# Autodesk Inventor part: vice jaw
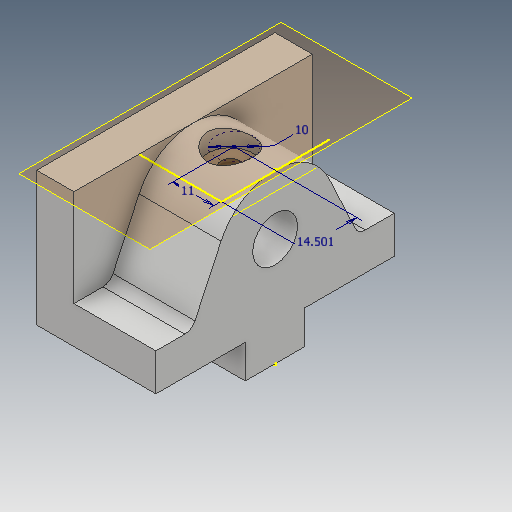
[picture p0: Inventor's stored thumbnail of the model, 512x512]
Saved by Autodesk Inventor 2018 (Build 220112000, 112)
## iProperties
Created: 2016-03
Part Number: vice jaw
Material: Generic
Document SubType Name: Modeling
Designer: Sandeep
Density: 1 g/cm^3
Appearance: Default
Author: Sandeep
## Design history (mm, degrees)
sketch "Sketch1"
  geometry: L1 (0, 0)-(-32, 0); L2 (-32, 0)-(-32, 36); L3 (-32, 36)-(-22, 36); L4 (-22, 36)-(-22, 10); L5 (-22, 10)-(0, 10); L6 (0, 10)-(0, 0)
  constraints: 12 end point, 5 perpendicular, 1 horizontal
  dimensions: "d0" = 36 distance between parallel lines of L1 L3; "d1" = 32 distance of L1.start L1.end; "d2" = 10 distance of L5.end L1.start; "d3" = 10 distance of L2.end L3.end
extrude "Extrusion1" new body sketch "Sketch1" stored distance "d4" = 64; taper "d5" = 0 deg
sketch "Sketch2"
  geometry: L1 (64, 10)-(64, 0) reference; L2 (64, 10)-(64, 0); L3 (64, 0)-(54.317, 0); L4 (64, 0)-(0, 0) reference; L5 (54.317, 0)-(46.501, -16.762); L6 (0, 0)-(0, 10); L7 (0, 10)-(64, 10); L8 (64, -26)-(0, -26) reference; L9 (0, 0)-(9.683, 0); L10 (32, 10)-(32, -39.451); L11 (9.683, 0)-(17.499, -16.762); A1 r 16 centre (32, -10) between (17.499, -16.762) and (46.501, -16.762); 1 further point
  constraints: 16 end point, 3 point on line, 2 collinear, 2 perpendicular, 2 point on circle, 2 symmetric about line, 2 tangent, 1 centre point, 1 coincident, 1 vertical
  dimensions: "d8" = 16 radius of A1; "d9" = 50 deg angle of L11 L5
extrude "Extrusion2" join sketch "Sketch2" stored distance "d10" = 32; taper "d11" = 0 deg
fillet "Fillet1" dims "d12" = 3
sketch "Sketch3"
  geometry: L1 (40, 0)-(40, 9); L2 (40, 9)-(24, 9); L3 (24, 9)-(24, 0); L4 (24, 0)-(40, 0); L5 (0, 0)-(64, 0) reference; L6 (32, 0)-(32, -54.171)
  constraints: 10 end point, 2 perpendicular, 2 vertical, 1 collinear, 1 point on line, 1 other
  dimensions: "d13" = 16 distance between parallel lines of L3 L1; "d14" = 9 distance of L2.end L3.end
extrude "Extrusion3" join sketch "Sketch3" stored distance "d15" = 32; taper "d16" = 0 deg
sketch "Sketch4"
  geometry: L1 (-24, 19)-(-40, 19) reference; L2 (-32, 19)-(-32, -29.453); C1 r 6 at (-32, -10); A1 r 16 centre (-32, -10) between (-46.501, -16.762) and (-17.499, -16.762) reference; 1 further point
  constraints: 2 end point, 1 centre point, 1 concentric, 1 midpoint, 1 point on line, 1 vertical
  dimensions: "d17" = 12 diameter of C1
extrude "Extrusion4" cut sketch "Sketch4" distance "d18" = 24; taper "d19" = 0 deg
sketch "Sketch6"
  geometry: 1 further point
workplane "Work Plane1"
sketch "Sketch7"
  geometry: L1 (14.501, 0)-(-14.501, 0) reference; L2 (14.501, 0)-(14.501, -22) reference; C1 r 5 at (0, -11); 1 further point
  constraints: 1 centre point
  dimensions: "d22" = 10 diameter of C1; "d23" = 11 distance from line of L1 C1.centre; "d24" = 14.50092 distance from line of C1.centre L2
workplane "Work Plane2"
hole "Hole1" diameter "d37" = 4.917; stored, may be unused: countersink angle "d41" = 90 deg, drill point angle "d43" = 118 deg; dims "d35" = 8, "d36" = 8, "d38" = 12, "d39" = 4, "d40" = 2, "d42" = 16
hole "Hole2" diameter "d46" = 4.917; stored, may be unused: countersink angle "d50" = 90 deg, drill point angle "d52" = 118 deg; dims "d44" = 8, "d45" = 8, "d47" = 12, "d48" = 4, "d49" = 2, "d51" = 16
hole "Hole3" diameter "d55" = 4.917; stored, may be unused: countersink angle "d59" = 82 deg, drill point angle "d61" = 118 deg; dims "d53" = 20, "d54" = 32, "d56" = 12, "d57" = 12, "d58" = 5, "d60" = 17.1
sketch "Sketch10"
  geometry: 1 further point
body "Solid1"
